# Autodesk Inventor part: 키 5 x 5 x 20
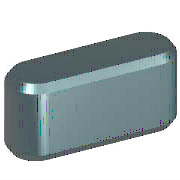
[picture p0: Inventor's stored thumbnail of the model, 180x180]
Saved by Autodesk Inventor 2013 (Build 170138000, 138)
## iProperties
IsCustomPart: 1
Created: 2012-02
Part Number: 키 5 x 5 x 20
Material: 강철, 연강
Description: 키 및 해당 키홈
Document SubType Name: Modeling
Standard: KS B 1311
Designer: mduedu
Standards Organization: KS
Language: ko-KR
Size Designation: 5 x 5 x 20
Categories: <MemberInstance><Categories><Category DisplayName="샤프트 부품" InternalName="7f7aeb1f-a693-4053-b835-cee3144e0d98" Mnemonic="SHFT"><Category DisplayName="키" Interna
Density: 1 g/cm^3
Author: mduedu
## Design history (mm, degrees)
workplane "Work Plane1"
workplane "Work Plane2"
sketch "스케치1"
  geometry: L1 (2.5, 2.5)-(17.5, 2.5); L2 (17.5, -2.5)-(2.5, -2.5); L3 (0, 9.4)-(0, -7.4) reference; L4 (-5, 0)-(30, 0) reference; L5 (20, 0)-(20, 7); A1 r 2.5 centre (2.5, 0) between (2.5, 2.5) and (2.5, -2.5); A2 r 2.5 centre (17.5, 0) between (17.5, -2.5) and (17.5, 2.5)
  constraints: 6 end point, 5 point on circle, 4 tangent, 3 point on line, 2 centre point, 1 horizontal, 1 parallel, 1 perpendicular
  dimensions: "d0" = 2.5 radius of A1 (= 0.5 x PB); "d13" = 2.5 radius of A2 (= 0.5 x PB); "d14" = 20 distance between parallel lines of L5 L3 (= NLG)
extrude "본체1" new body sketch "스케치1" taper "d3" = 0 deg; stored distance "d4" = 10
workplane "Work Plane3"
body "Solid1"
chamfer "모따기1" distance "d8" = 0.4 (= PHH); stored, may be unused: second distance "d9" = 0.4 (= PHH), angle "d15" = 45 deg
other parameters: "d1" = -3 (= -PNT), "d2" = 2 (= PH - PNT), "NLG" = 20 [user parameter; used in 3 equation terms], "PB" = 5 [user parameter; used in 2 equation terms], "PNT" = 3 [user parameter; used in 2 equation terms], "PH" = 5 [user parameter; used in 1 equation term], "PHH" = 0.4 [user parameter; used in 2 equation terms], "d10" = 0, "d16" = 0, "d17" = 0, "d18" = 0, "WDMIN" = 12 [user parameter], "WDMAX" = 17 [user parameter], "RR" = 0.16 [user parameter], "PUEB" = 2.3 [user parameter]
